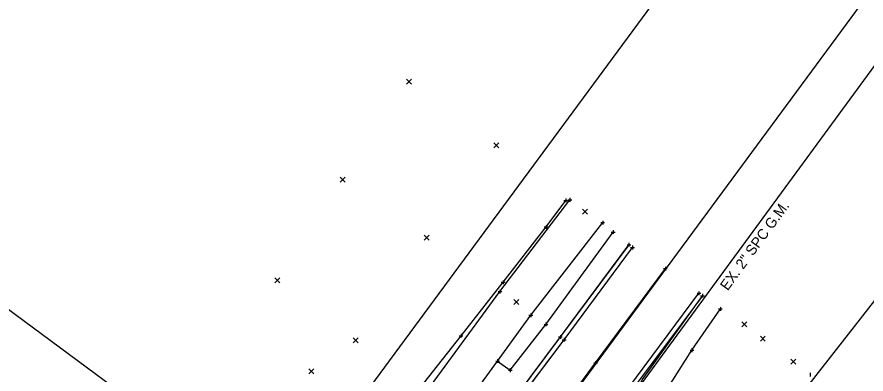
# Model space of a CAD drawing. Extents: x 1324089 to 1329959, y 459099 to 462017.
# Drawn here: x 1325717.7 to 1325945.3, y 461050 to 461145.6 of the extents above; entities that cross this region are included whole.
import ezdxf

# ---------------------------------------------------------------- set-up
doc = ezdxf.new("R2010")
doc.units = 0
for name, color, linetype in [('DR_X_Ditch', 7, 'Continuous'), ('DV_X_Property_Line', 7, 'Continuous'), ('PM_X_CL_Double_Solid', 7, 'Continuous'), ('PM_X_Edge_Line', 7, 'Continuous'), ('PM_X_Surveyed_Line', 7, 'Continuous'), ('PV_X_EOP', 7, 'Continuous'), ('RW_X_CL', 7, 'Continuous'), ('RW_X_Fee_RW', 7, 'Continuous'), ('SV_X_Break_Lines', 7, 'Continuous'), ('SV_X_Random_Point', 7, 'Continuous'), ('SV_X_Shot_Marker', 7, 'Continuous'), ('UT_X_Gas', 7, 'Continuous'), ('UT_X_Gas_Text', 7, 'Continuous'), ('UT_X_Telecom', 7, 'Continuous')]:
    doc.layers.add(name, color=color, linetype=linetype)

msp = doc.modelspace()

# ---------------------------------------------------------------- linework, layer by layer
at = {"layer": 'DR_X_Ditch'}
msp.add_lwpolyline([(1325889.73, 461043.23), (1325891.87, 461045.63), (1325898.65, 461056.34), (1325906.3, 461067.38)], dxfattribs=at)
at = {"layer": 'DV_X_Property_Line'}
msp.add_line((1325788.03, 461013.56), (1325636.38, 461125.52), dxfattribs=at)
at = {"layer": 'PM_X_CL_Double_Solid'}
for p, q in [((1325872.84, 461052.92), (1325891.56, 461078.18)), ((1325852.52, 461025.38), (1325872.84, 461052.92))]:
    msp.add_line(p, q, dxfattribs=at)
at = {"layer": 'PM_X_Edge_Line'}
for p, q in [((1325864.41, 461059.13), (1325882.73, 461083.84)), ((1325881.76, 461046.3), (1325900.52, 461071.57)), ((1325843.8, 461031.8), (1325864.41, 461059.13))]:
    msp.add_line(p, q, dxfattribs=at)
at = {"layer": 'PM_X_Surveyed_Line'}
for points in [[(1325476.47, 460534.64), (1325497.31, 460562.92), (1325518.31, 460591.4), (1325539.27, 460619.83), (1325559.79, 460647.38), (1325579.72, 460674.06), (1325600.34, 460701.82), (1325621.69, 460730.61), (1325640.88, 460756.72), (1325660.89, 460784.38), (1325681.35, 460812.31), (1325701.97, 460840.18), (1325722.79, 460868.47), (1325742.91, 460895.72), (1325762.59, 460922.34), (1325781.84, 460948.46), (1325803.18, 460977.15), (1325823.47, 461004.35), (1325843.8, 461031.8), (1325864.41, 461059.13), (1325882.73, 461083.84)], [(1325487.31, 460531.49), (1325505.56, 460556.21), (1325527.38, 460585.35), (1325547.88, 460612.77), (1325568.5, 460640.75), (1325588.53, 460667.69), (1325609.18, 460695.62), (1325629.78, 460723.42), (1325649.85, 460750.69), (1325670.06, 460778.36), (1325689.99, 460805.97), (1325710.73, 460833.83), (1325731.56, 460861.89), (1325751.85, 460889.28), (1325771.48, 460915.92), (1325790.62, 460941.82), (1325811.71, 460970.27), (1325832.15, 460997.96), (1325852.52, 461025.38), (1325872.84, 461052.92), (1325891.56, 461078.18)], [(1325496.02, 460524.26), (1325516.97, 460552.29), (1325536.74, 460578.69), (1325557.07, 460606.11), (1325577.39, 460633.55), (1325597.52, 460661.26), (1325617.8, 460689.11), (1325638.48, 460716.73), (1325658.71, 460744.05), (1325678.83, 460771.46), (1325699, 460798.96), (1325719.69, 460827.08), (1325740.27, 460854.83), (1325759.31, 460880.54), (1325780.72, 460909.4), (1325799.76, 460935.26), (1325820.52, 460963.73), (1325840.72, 460991.07), (1325861.64, 461019.05), (1325881.76, 461046.3), (1325900.52, 461071.57)]]:
    msp.add_lwpolyline(points, dxfattribs=at)
at = {"layer": 'PV_X_EOP'}
for points in [[(1325599.85, 460702.28), (1325620.93, 460731.2), (1325640.13, 460757.25), (1325660.19, 460784.82), (1325680.81, 460812.72), (1325701.43, 460840.57), (1325722.31, 460868.78), (1325742.47, 460895.99), (1325762.18, 460922.64), (1325781.4, 460948.97), (1325780.32, 460951.92), (1325801.56, 460978.26), (1325816.22, 460999.3), (1325818.01, 460999.23), (1325822.67, 461005.05), (1325842.97, 461032.46), (1325863.41, 461059.87), (1325881.77, 461084.58), (1325817.82, 460998.91)], [(1325599.89, 460659.68), (1325606.14, 460668.13), (1325605.32, 460670.67), (1325618.61, 460688.48), (1325639.21, 460716.24), (1325659.3, 460743.54), (1325679.42, 460770.95), (1325699.67, 460798.43), (1325720.28, 460826.77), (1325740.7, 460854.48), (1325759.66, 460880.4), (1325781, 460909.09), (1325800.15, 460934.9), (1325820.98, 460963.36), (1325841.65, 460990.38), (1325860.1, 461014.66), (1325864.14, 461018.09), (1325883.16, 461043.3), (1325885.35, 461048.43), (1325901.49, 461070.93), (1325836.64, 460984.43)]]:
    msp.add_lwpolyline(points, dxfattribs=at)
at = {"layer": 'RW_X_CL'}
msp.add_line((1325484.96, 460527.54), (1326057.93, 461303.2), dxfattribs=at)
at = {"layer": 'RW_X_Fee_RW'}
for p, q in [((1325448.76, 460554.27), (1326011.05, 461315.47)), ((1325947.56, 461069.64), (1325722.65, 460781.99))]:
    msp.add_line(p, q, dxfattribs=at)
at = {"layer": 'SV_X_Break_Lines'}
for points in [[(1325806.37, 461018.16), (1325826.87, 461044.35), (1325847.2, 461072.04), (1325865.93, 461096.61)], [(1325799.31, 461012.32), (1325808.16, 461008.89), (1325817.66, 461014.86), (1325835.56, 461038.28), (1325846.55, 461053.41), (1325855.47, 461065.69), (1325874.76, 461090.52)], [(1325846.55, 461053.41), (1325849.97, 461050.98), (1325859.5, 461063.23), (1325877.54, 461087.98)]]:
    msp.add_lwpolyline(points, dxfattribs=at)
at = {"layer": 'SV_X_Random_Point'}
for p, q in [((1325822.15, 461127.58), (1325823.48, 461128.91)), ((1325822.15, 461128.91), (1325823.48, 461127.58)), ((1325845.52, 461110.56), (1325846.85, 461111.9)), ((1325845.52, 461111.9), (1325846.85, 461110.56)), ((1325804.36, 461101.3), (1325805.69, 461102.64)), ((1325804.36, 461102.64), (1325805.69, 461101.3)), ((1325869.32, 461092.74), (1325870.66, 461094.07)), ((1325869.32, 461094.07), (1325870.66, 461092.74)), ((1325826.85, 461085.81), (1325828.18, 461087.15)), ((1325826.85, 461087.15), (1325828.18, 461085.81)), ((1325786.81, 461074.33), (1325788.14, 461075.67)), ((1325786.81, 461075.67), (1325788.14, 461074.33)), ((1325850.94, 461068.54), (1325852.27, 461069.88)), ((1325850.94, 461069.88), (1325852.27, 461068.54)), ((1325912.06, 461062.57), (1325913.4, 461063.91)), ((1325912.06, 461063.91), (1325913.4, 461062.57)), ((1325917, 461058.72), (1325918.33, 461060.05)), ((1325917, 461060.05), (1325918.33, 461058.72)), ((1325807.81, 461058.3), (1325809.14, 461059.63)), ((1325807.81, 461059.63), (1325809.14, 461058.3)), ((1325925.13, 461052.61), (1325926.47, 461053.94)), ((1325925.13, 461053.94), (1325926.47, 461052.61)), ((1325795.92, 461049.96), (1325797.25, 461051.3)), ((1325795.92, 461051.3), (1325797.25, 461049.96))]:
    msp.add_line(p, q, dxfattribs=at)
at = {"layer": 'SV_X_Shot_Marker'}
for p, q in [((1325864.32, 461096.45), (1325865.32, 461096.45)), ((1325864.82, 461096.95), (1325864.82, 461095.95)), ((1325864.82, 461096.45), (1325864.82, 461096.45)), ((1325865.43, 461096.61), (1325866.43, 461096.61)), ((1325865.93, 461097.11), (1325865.93, 461096.11)), ((1325865.93, 461096.61), (1325865.93, 461096.61)), ((1325859.05, 461089.34), (1325860.05, 461089.34)), ((1325859.55, 461089.84), (1325859.55, 461088.84)), ((1325859.55, 461089.34), (1325859.55, 461089.34)), ((1325874.26, 461090.52), (1325875.26, 461090.52)), ((1325874.76, 461091.02), (1325874.76, 461090.02)), ((1325874.76, 461090.52), (1325874.76, 461090.52)), ((1325877.04, 461087.98), (1325878.04, 461087.98)), ((1325877.54, 461088.48), (1325877.54, 461087.48)), ((1325877.54, 461087.98), (1325877.54, 461087.98)), ((1325881.77, 461085.08), (1325881.77, 461084.08)), ((1325881.27, 461084.58), (1325882.27, 461084.58)), ((1325881.77, 461084.58), (1325881.77, 461084.58)), ((1325882.23, 461083.84), (1325883.23, 461083.84)), ((1325882.73, 461084.34), (1325882.73, 461083.34)), ((1325882.73, 461083.84), (1325882.73, 461083.84)), ((1325891.06, 461078.18), (1325892.06, 461078.18)), ((1325891.56, 461078.68), (1325891.56, 461077.68)), ((1325891.56, 461078.18), (1325891.56, 461078.18)), ((1325847.55, 461074.54), (1325848.55, 461074.54)), ((1325848.05, 461075.04), (1325848.05, 461074.04)), ((1325848.05, 461074.54), (1325848.05, 461074.54)), ((1325846.7, 461072.04), (1325847.7, 461072.04)), ((1325847.2, 461072.54), (1325847.2, 461071.54)), ((1325847.2, 461072.04), (1325847.2, 461072.04)), ((1325900.02, 461071.57), (1325901.02, 461071.57)), ((1325900.52, 461072.07), (1325900.52, 461071.07)), ((1325900.52, 461071.57), (1325900.52, 461071.57)), ((1325901.49, 461071.43), (1325901.49, 461070.43)), ((1325900.99, 461070.93), (1325901.99, 461070.93)), ((1325901.49, 461070.93), (1325901.49, 461070.93)), ((1325905.8, 461067.38), (1325906.8, 461067.38)), ((1325906.3, 461067.88), (1325906.3, 461066.88)), ((1325906.3, 461067.38), (1325906.3, 461067.38)), ((1325854.97, 461065.69), (1325855.97, 461065.69)), ((1325855.47, 461066.19), (1325855.47, 461065.19)), ((1325855.47, 461065.69), (1325855.47, 461065.69)), ((1325859, 461063.23), (1325860, 461063.23)), ((1325859.5, 461063.73), (1325859.5, 461062.73)), ((1325859.5, 461063.23), (1325859.5, 461063.23)), ((1325836.27, 461060.22), (1325837.27, 461060.22)), ((1325836.77, 461060.72), (1325836.77, 461059.72)), ((1325836.77, 461060.22), (1325836.77, 461060.22)), ((1325862.91, 461059.87), (1325863.91, 461059.87)), ((1325863.41, 461060.37), (1325863.41, 461059.37)), ((1325863.41, 461059.87), (1325863.41, 461059.87)), ((1325863.91, 461059.13), (1325864.91, 461059.13)), ((1325864.41, 461059.63), (1325864.41, 461058.63)), ((1325864.41, 461059.13), (1325864.41, 461059.13)), ((1325898.15, 461056.34), (1325899.15, 461056.34)), ((1325898.65, 461056.84), (1325898.65, 461055.84)), ((1325898.65, 461056.34), (1325898.65, 461056.34)), ((1325846.05, 461053.41), (1325847.05, 461053.41)), ((1325846.05, 461053.41), (1325847.05, 461053.41)), ((1325846.55, 461053.91), (1325846.55, 461052.91)), ((1325846.55, 461053.91), (1325846.55, 461052.91)), ((1325846.55, 461053.41), (1325846.55, 461053.41)), ((1325846.55, 461053.41), (1325846.55, 461053.41)), ((1325872.34, 461052.92), (1325873.34, 461052.92)), ((1325872.84, 461053.42), (1325872.84, 461052.42)), ((1325872.84, 461052.92), (1325872.84, 461052.92)), ((1325849.47, 461050.98), (1325850.47, 461050.98)), ((1325849.97, 461051.48), (1325849.97, 461050.48)), ((1325849.97, 461050.98), (1325849.97, 461050.98)), ((1325930.37, 461050.25), (1325930.37, 461049.25))]:
    msp.add_line(p, q, dxfattribs=at)
at = {"layer": 'UT_X_Gas'}
msp.add_line((1325756.11, 460871.47), (1326071.48, 461301.36), dxfattribs=at)
at = {"layer": 'UT_X_Telecom'}
msp.add_lwpolyline([(1325797.83, 461007.22), (1325801.34, 461011.2), (1325805.93, 461017.4), (1325815.85, 461032.07), (1325826.76, 461047.52), (1325836.77, 461060.22), (1325848.05, 461074.54), (1325859.55, 461089.34), (1325864.82, 461096.45)], dxfattribs=at)

# ---------------------------------------------------------------- texts
at = {"layer": 'UT_X_Gas_Text'}
msp.add_text('EX. 2" SPC G.M.', height=2.8, rotation=53.9419, dxfattribs=at).set_placement((1325908.23, 461072.09))

doc.saveas('drawing.dxf')
